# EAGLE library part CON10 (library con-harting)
CONNECTOR
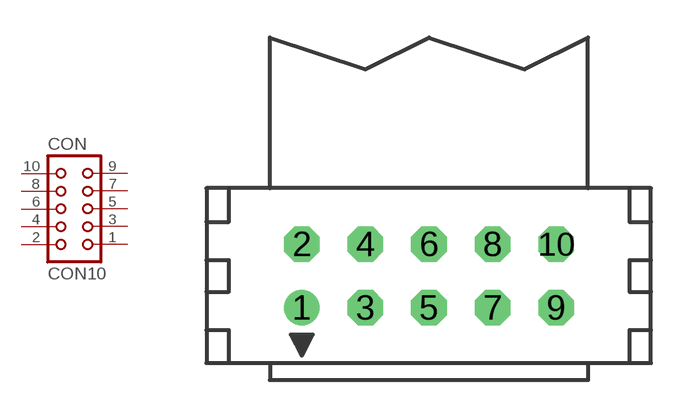
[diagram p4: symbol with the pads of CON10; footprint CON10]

Designator prefix CON

## CON10 (OC_FARNELL: unknown; OC_NEWARK: unknown)  [CON10]
1  1  pas
2  2  pas
3  3  pas
4  4  pas
5  5  pas
6  6  pas
7  7  pas
8  8  pas
9  9  pas
10  10  pas

## Footprint CON10 (pad centres in mm)
CONNECTOR
drill 0.914 round: 1 -5.08,-1.27
drill 0.914 octagon: 2 -5.08,1.27; 3 -2.54,-1.27; 4 -2.54,1.27; 5 0,-1.27; 6 0,1.27; 7 2.54,-1.27; 8 2.54,1.27; 9 5.08,-1.27; 10 5.08,1.27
